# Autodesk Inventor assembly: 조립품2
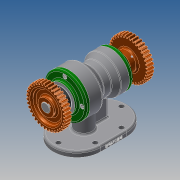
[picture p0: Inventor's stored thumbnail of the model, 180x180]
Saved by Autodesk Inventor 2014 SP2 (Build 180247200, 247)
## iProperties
Created: 2020-01
Part Number: 조립품2
Document SubType Name: Assembly
Designer: kb542-10
Author: kb542-10
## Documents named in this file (13)
- C:\Users\kb542-10\Desktop\700104V1035\조립품2.iam
- C:\Users\kb542-10\Desktop\700104V1035\본체.ipt
- C:\Users\kb542-10\Desktop\700104V1035\멈춤나사 M3.ipt
- C:\Users\kb542-10\Desktop\700104V1035\스퍼기어.ipt
- C:\Users\kb542-10\Desktop\700104V1035\축.ipt
- C:\Users\kb542-10\Desktop\700104V1035\키 5 x 5 x 18.ipt
- C:\Users\kb542-10\Desktop\700104V1035\베어링 6205.ipt
- C:\Users\kb542-10\Desktop\700104V1035\볼트 M4.ipt
- C:\Users\kb542-10\Desktop\700104V1035\앞커버.ipt
- C:\Users\kb542-10\Desktop\700104V1035\오일 실 25 38 8.ipt
- C:\Users\kb542-10\Desktop\700104V1035\뒤커버.ipt
- C:\Users\kb542-10\Desktop\700104V1035\베어링 6203.ipt
- C:\Users\kb542-10\Desktop\700104V1035\오일 실 17 30 8.ipt
